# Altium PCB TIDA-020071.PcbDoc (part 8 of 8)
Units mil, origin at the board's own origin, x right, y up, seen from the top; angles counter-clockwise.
Board outline 5750 x 4050 mil, 6 copper layers (Top Layer, GND PLANE-1, SIGNAL LAYER, SIGNAL/POWER LAYER, GND PLANE-2, Bottom Layer), stack 59.616 mil thick; 776 components, 498 nets, 2205 pads, 871 vias.
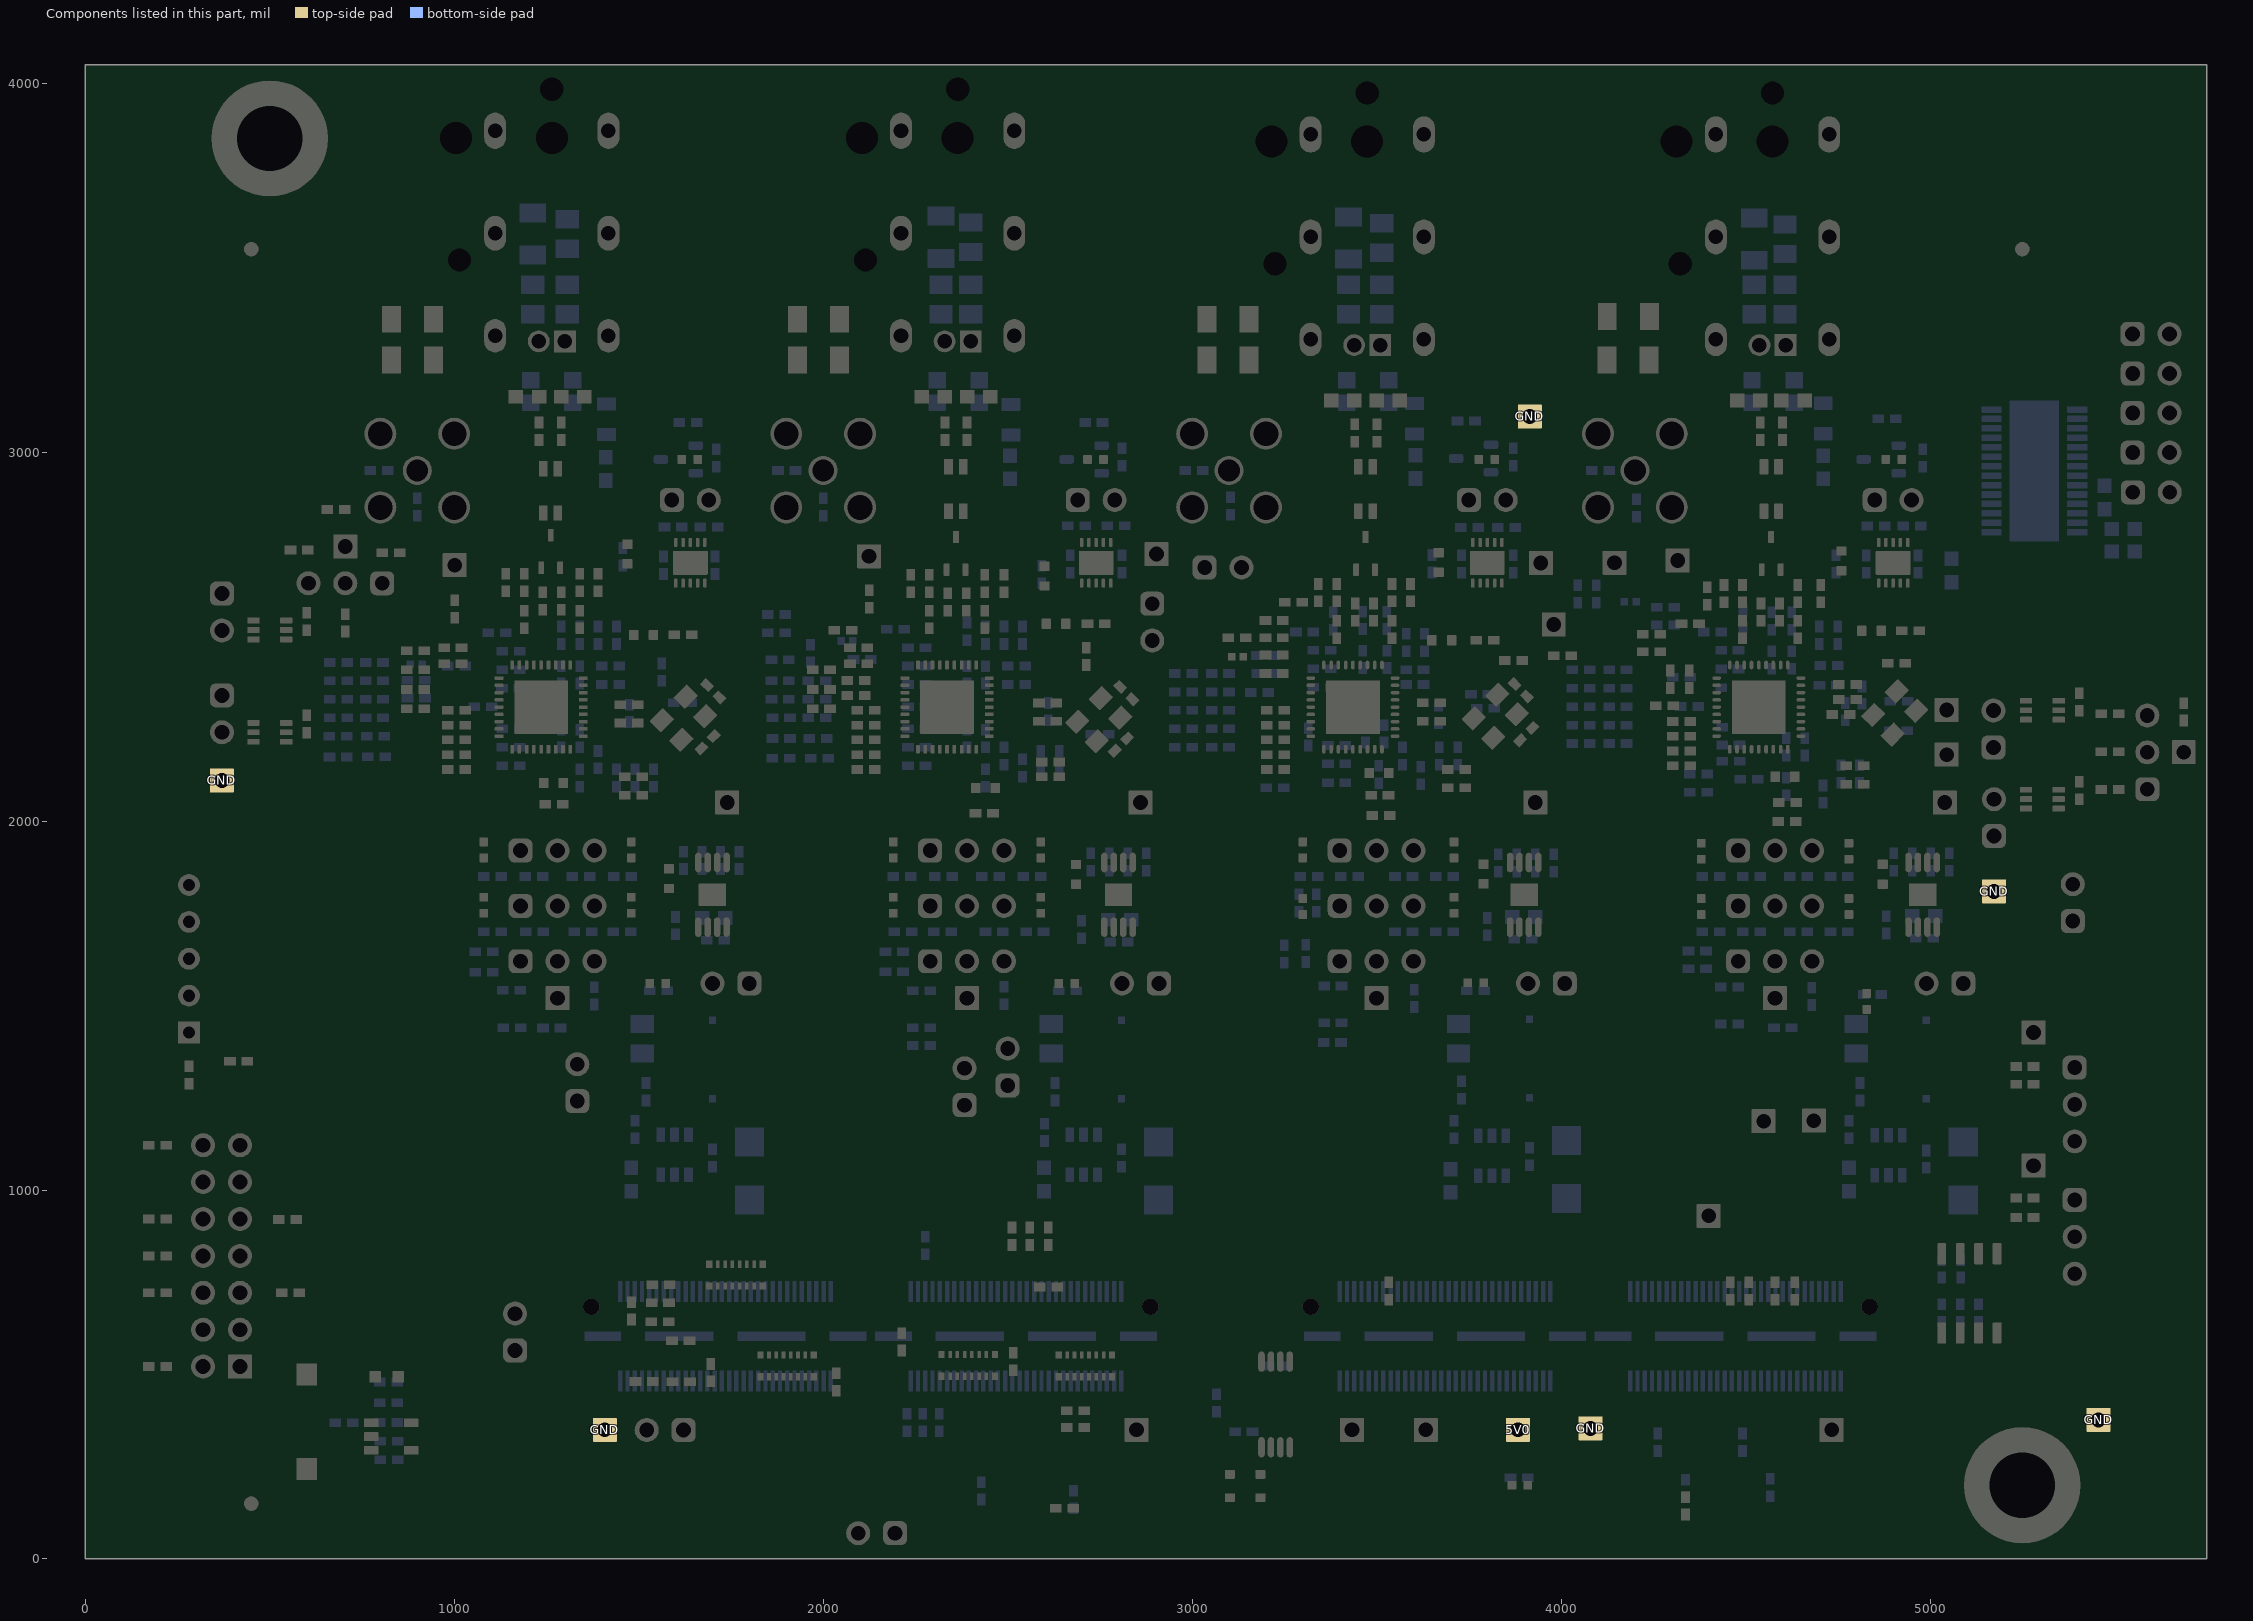
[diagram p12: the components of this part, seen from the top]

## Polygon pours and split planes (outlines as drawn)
GND on Bottom Layer "BOTTOM_LAYER_GND_P145" (solid, remove dead copper, pour order 145): 4467.17,3701.08 4467.44,3700.81 4467.44,3610.7 4491.13,3587.02 4644.4,3587.02 4659.1,3601.72 4659.1,3705.17 4639.77,3724.5 4486.23,3724.5 4484.6,3722.86
NetC154_1 on Bottom Layer "BOTTOM_LAYER_NETC154_1_P148" (solid, remove dead copper, pour order 148): 4533.65,3575.43 4491.63,3575.43 4471.04,3554.84 4471.04,3434.17 4495.8,3409.41 4644.31,3409.41 4664.76,3429.86 4664.76,3543.94 4633.27,3575.43
GND on Bottom Layer "BOTTOM_LAYER_GND_P146" (solid, remove dead copper, pour order 146): 3372.71,3706.71 3372.98,3706.44 3372.98,3616.33 3396.66,3592.65 3549.94,3592.65 3564.64,3607.35 3564.64,3710.8 3545.31,3730.13 3391.76,3730.13 3390.13,3728.49
NetC143_1 on Bottom Layer "BOTTOM_LAYER_NETC143_1_P147" (solid, remove dead copper, pour order 147): 3439.18,3581.06 3397.17,3581.06 3376.58,3560.47 3376.58,3439.8 3401.34,3415.04 3549.85,3415.04 3570.3,3435.49 3570.3,3549.57 3538.81,3581.06
NetC165_1 on Bottom Layer "BOTTOM_LAYER_NETC165_1_P144" (solid, remove dead copper, pour order 144): 2323.83,3582.33 2281.81,3582.33 2261.22,3561.75 2261.22,3441.07 2285.98,3416.32 2434.49,3416.32 2454.94,3436.76 2454.94,3550.84 2423.45,3582.33
GND on Bottom Layer "BOTTOM_LAYER_GND_P149" (solid, remove dead copper, pour order 149): 2257.35,3707.99 2257.62,3707.72 2257.62,3617.6 2281.31,3593.92 2434.58,3593.92 2449.28,3608.62 2449.28,3712.07 2429.95,3731.4 2276.41,3731.4 2274.78,3729.77
GND on Bottom Layer "BOTTOM_LAYER_GND_P150" (solid, remove dead copper, pour order 150): 1163.47,3710.34 1163.74,3710.07 1163.74,3619.95 1187.42,3596.27 1340.7,3596.27 1355.4,3610.97 1355.4,3714.42 1336.07,3733.75 1182.52,3733.75 1180.89,3732.12
NetC173_1 on Bottom Layer "BOTTOM_LAYER_NETC173_1_P151" (solid, remove dead copper, pour order 151): 1229.94,3584.68 1187.92,3584.68 1167.34,3564.1 1167.34,3443.42 1192.1,3418.67 1340.61,3418.67 1361.06,3439.11 1361.06,3553.2 1329.57,3584.68
GND on Bottom Layer "BOTTOM_LAYER_GND_P185" (solid, remove dead copper, pour order 185): 5717.1,3150 26,3150 26,50 5717.1,50
GND720-2 on Bottom Layer "BOTTOM_LAYER_GND720-2_P184" (solid, remove dead copper, pour order 184): 4198.5,3173.44 4198.5,4000 4828.58,4000 4828.43,3173.44
GND720-1 on Bottom Layer "BOTTOM_LAYER_GND720-1_P183" (solid, remove dead copper, pour order 183): 3100,3173.44 3100,4000 3730.08,4000 3729.92,3173.44
GND720-3 on Bottom Layer "BOTTOM_LAYER_GND720-3_P179" (solid, remove dead copper, pour order 179): 1990,3183.44 1990,4010 2620.08,4010 2619.92,3183.44
GND720-4 on Bottom Layer "BOTTOM_LAYER_GND720-4_P182" (solid, remove dead copper, pour order 182): 890.24,3180 890.24,4010 1520.32,4010 1520.16,3180
NetC37_1 on Bottom Layer "BOTTOM_LAYER_NETC37_1_P152" (solid, remove dead copper, pour order 152): 4860.63,1280 4860.63,1209.68 4860.63,1050 5170,1050 5170,1220 5110,1280
NetC3_1 on Bottom Layer "BOTTOM_LAYER_NETC3_1_P154" (solid, remove dead copper, pour order 154): 3780,1280 3780,1209.68 3780,1050 4089.37,1050 4089.37,1220 4029.37,1280
+3V3_REG-4 on Bottom Layer "BOTTOM_LAYER_+3V3_REG-4_P178" (solid, remove dead copper, pour order 178): 1470,1440 1470,1600 1537.01,1665.39 1718.4,1665.39 1824.02,1563.12 1824.02,1440
+3V3_REG-1 on Bottom Layer "BOTTOM_LAYER_+3V3_REG-1_P177" (solid, remove dead copper, pour order 177): 3690,1440 3690,1600 3757.01,1665.39 3938.4,1665.39 4044.02,1563.12 4044.02,1440
+3V3_REG-3 on Bottom Layer "BOTTOM_LAYER_+3V3_REG-3_P172" (solid, remove dead copper, pour order 172): 2580,1440 2580,1600 2647.01,1665.39 2828.4,1665.39 2934.02,1563.12 2934.02,1440
NetC105_1 on Bottom Layer "BOTTOM_LAYER_NETC105_1_P171" (solid, remove dead copper, pour order 171): 1570,1280 1570,1209.68 1570,1050 1879.37,1050 1879.37,1220 1819.37,1280
NetC71_1 on Bottom Layer "BOTTOM_LAYER_NETC71_1_P155" (solid, remove dead copper, pour order 155): 2680,1280 2680,1209.68 2680,1050 2989.37,1050 2989.37,1220 2929.37,1280
+3V3_REG-2 on Bottom Layer "BOTTOM_LAYER_+3V3_REG-2_P153" (solid, remove dead copper, pour order 153): 4760,1440 4760,1600 4827.01,1665.39 5008.4,1665.39 5114.02,1563.12 5114.02,1440
GND on Top Layer "TOP_LAYER_GND_P173" (solid, remove dead copper, pour order 173): 5717.1,3150 26,3150 26,50 5717.1,50
PWM_Main on Top Layer "TOP_LAYER_NONET_P-001" (solid, remove dead copper, pour order 170): 253.05,1317.03 385.09,1317.03 410.13,1342.07 410.13,1444.21 379.38,1474.96 241.65,1474.96 231.23,1464.55 231.23,1338.85
GND720-2 on Top Layer "TOP_LAYER_GND720-2_P169" (solid, remove dead copper, pour order 169): 4198.5,3173.44 4198.5,4000 4828.58,4000 4828.43,3173.44
GND720-1 on Top Layer "TOP_LAYER_GND720-1_P168" (solid, remove dead copper, pour order 168): 3100,3173.44 3100,4000 3730.08,4000 3729.92,3173.44
GND720-3 on Top Layer "TOP_LAYER_GND720-3_P142" (solid, remove dead copper, pour order 142): 1990,3183.44 1990,4010 2620.08,4010 2619.92,3183.44
GND720-4 on Top Layer "TOP_LAYER_GND720-4_P143" (solid, remove dead copper, pour order 143): 890.24,3180 890.24,4010 1520.32,4010 1520.16,3180
GND on GND PLANE-1 "GND_PLANE-1_GND_P174" (solid, remove dead copper, pour order 174): 5717.1,4009.44 26,4009.44 26,50 5717.1,50
GND on GND PLANE-1 "GND_PLANE-1_GND_P159" (solid, remove dead copper, pour order 159): 4500,3520 4643.84,3520 4643.84,2720 4500,2720
GND on GND PLANE-1 "GND_PLANE-1_GND_P156" (solid, remove dead copper, pour order 156): 1180,3350 1350,3350 1350,2727.01 1180,2727.01
GND on GND PLANE-1 "GND_PLANE-1_GND_P158" (solid, remove dead copper, pour order 158): 3410,3520.47 3554.73,3520.47 3554.73,2722.64 3410,2722.64
GND on GND PLANE-1 "GND_PLANE-1_GND_P157" (solid, remove dead copper, pour order 157): 2280,3360 2450,3360 2450,2721.16 2280,2721.16
5V0 on SIGNAL/POWER LAYER "SIGNAL/POWER_LAYER_5V0_P175" (solid, remove dead copper, pour order 175): 5717.1,3150 26,3150 26,50 5717.1,50
Vpu-3 on SIGNAL/POWER LAYER "SIGNAL/POWER_LAYER_VPU-3_P162" (solid, remove dead copper, pour order 162): 1830,2233.82 1830,2276.38 1894.44,2340.82 2094.3,2340.82 2118.3,2316.83 2118.3,2260.52 2145,2233.82 2650,2233.82 2650,2027.51 2370,1747.51 2370,1637.65 2262.35,1530 2221.28,1530 2130,1621.28 2130,1883.82 1830,2183.82
Vpu-4 on SIGNAL/POWER LAYER "SIGNAL/POWER_LAYER_VPU-4_P160" (solid, remove dead copper, pour order 160): 627.67,2189.73 627.67,2207.17 643.3,2222.8 731.42,2222.8 1013.15,1941.07 1131.04,1941.07 1156.39,1915.72 1156.39,1876.25 1424.22,1876.25 1545.72,1997.75 1545.72,2013.58 1535.31,2024 1407.14,2024 1394.55,2011.41 1353.29,2011.41 1286.18,2078.52 1286.18,2141.98 1352.79,2208.59 1540.97,2208.59 1670.6,2078.96 1670.6,1915.65 1279.47,1531.04 1279.35,1520.21 1101.73,1519.96 1000,1621.69 1000,1817.4
Vpu-2 on SIGNAL/POWER LAYER "SIGNAL/POWER_LAYER_VPU-2_P161" (solid, remove dead copper, pour order 161): 4330,2028.52 4423.88,2122.4 4655.46,2122.4 4666.36,2111.5 4815.01,2111.5 4830,2096.51 4830,1829.4 4530.1,1529.5 4396.02,1529.5 4330,1590
Vpu-1 on SIGNAL/POWER LAYER "SIGNAL/POWER_LAYER_VPU-1_P163" (solid, remove dead copper, pour order 163): 2920,2160 2920,2210 3740,2210 3740,2010 3390,1660 3390,1550 3360,1520 3330.46,1520 3240,1610.46 3240,1840
GND on GND PLANE-2 "GND_PLANE-2_GND_P176" (solid, remove dead copper, pour order 176): 5717.1,3150 26,3150 26,50 5717.1,50
GND on GND PLANE-2 "GND_PLANE-2_GND_P164" (solid, remove dead copper, pour order 164): 4500,3520 4643.84,3520 4643.84,2720 4500,2720
GND on GND PLANE-2 "GND_PLANE-2_GND_P165" (solid, remove dead copper, pour order 165): 3410,3520.47 3554.73,3520.47 3554.73,2722.64 3410,2722.64
GND on GND PLANE-2 "GND_PLANE-2_GND_P166" (solid, remove dead copper, pour order 166): 2280,3360 2450,3360 2450,2721.16 2280,2721.16
GND on GND PLANE-2 "GND_PLANE-2_GND_P167" (solid, remove dead copper, pour order 167): 1180,3350 1350,3350 1350,2727.01 1180,2727.01

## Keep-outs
GND PLANE-1:
  circle w10: c450,150 r39.27
GND PLANE-2:
  circle w10: c450,150 r39.27
Keep-Out Layer:
  text ".Layer_Name" at 877,-858.49 h60

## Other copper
Top Layer:
  rectangle net GND: 4450.72,2224.36 4620.01,2393.66
  rectangle net GND: 3350.72,2224.36 3520.01,2393.66
  rectangle net GND: 2250.72,2224.36 2420.01,2393.66
  rectangle net GND: 1150.72,2224.36 1320.01,2393.66
  pour cut-out: 2306.19,3119.3 2413.81,3119.3 2413.81,2987.79 2404.32,2987.79 2404.32,2802.37 2400.9,2802.37 2400.9,2651.33 2313.81,2651.33 2313.81,2697.75 2320.75,2697.75 2320.75,2802.37 2317.33,2802.37 2317.33,2987.79 2306.19,2987.79
  pour cut-out: 4489.7,3340 4660,3340 4660,3150 4490.27,3150
  pour cut-out: 3389.7,3340 3560,3340 3560,3150 3390.27,3150
  pour cut-out: 1206.19,3119.3 1313.81,3119.3 1313.81,2987.79 1304.32,2987.79 1304.32,2802.37 1300.9,2802.37 1300.9,2651.33 1213.81,2651.33 1213.81,2697.75 1220.75,2697.75 1220.75,2802.37 1217.33,2802.37 1217.33,2987.79 1206.19,2987.79
  pour cut-out: 4439,2406 4439,2210.7 4633.7,2210.7 4633.7,2406
  pour cut-out: 3339,2406 3339,2210.7 3533.7,2210.7 3533.7,2406
  pour cut-out: 1139,2406 1139,2210.7 1333.7,2210.7 1333.7,2406
  pour cut-out: 2239,2406 2239,2210.7 2433.7,2210.7 2433.7,2406
  pour cut-out: 1179.42,3350 1349.72,3350 1349.72,3160 1179.99,3160
  pour cut-out: 2279.7,3350 2450,3350 2450,3160 2280.27,3160
  pour cut-out: 4526.82,2927.33 4613.81,2927.33 4613.81,2872.59 4526.82,2872.59
  pour cut-out: 3426.19,2927.33 3513.18,2927.33 3513.18,2872.59 3426.19,2872.59
  pour cut-out: 2316.19,2927.33 2403.18,2927.33 2403.18,2872.59 2316.19,2872.59
  pour cut-out: 1217.33,2922.45 1304.32,2922.45 1304.32,2870 1302.03,2867.71 1217.33,2867.71
  text ".Layer_Name" at 896.98,-852.79 h60
GND PLANE-1:
  text ".Layer_Name" at 905.5,-854.9 h60
SIGNAL LAYER:
  text ".Layer_Name" at 896.98,-852.79 h60
SIGNAL/POWER LAYER:
  text ".Layer_Name" at 888.5,-856.4 h60
GND PLANE-2:
  text ".Layer_Name" at 896.98,-852.79 h60
Bottom Layer:
  text ".Layer_Name" at 896.98,-852.79 h60

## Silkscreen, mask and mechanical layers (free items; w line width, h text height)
Top Overlay:
  drawing of 284 lines, arcs and shapes, not listed
  text "EN PoDL J8" at 5149.22,3309.06 h60
  text "EN PoDL J7" at 5149.22,3200.63 h60
  text "EN PoDL J9" at 5149.22,3089.33 h60
  text "EN PoDL J10" at 5149.22,2981.58 h60
  text "1V0" at 2797.75,2962.25 h60
  text "1V0" at 3861.61,2960.1 h60
  text "1V0" at 4965.16,2957.7 h60
  text "1V0" at 1691.81,2942.6 h60
  text "Diag EN" at 5149.22,2868.9 h60
  text "SoC" at 5542.01,2780.2 h60
  text "MDIO1/2" at 5432.06,2727.24 h60
  text "PHY" at 5535.98,2676.28 h60
  text "PHY" at 203.1,2603.9 h60
  text "SoC" at 5542.68,2581.08 h60
  text "MDIO3/4" at 106.97,2544.06 h60
  text "MDC1/2" at 5452.17,2525.43 h60
  text "SoC" at 206.01,2490.46 h60
  text "PHY" at 5542.68,2472.47 h60
  text "PHY" at 201.65,2331.47 h60
  text "MDC3/4" at 106.13,2273.04 h60
  text "SoC" at 205.52,2215.61 h60
  text "MASTER" at 828.76,1900 h60
  text "MASTER" at 1940.09,1900 h60
  text "MASTER" at 3052.63,1900 h60
  text "MASTER" at 4130,1900 h60
  text "GND" at 344.12,1800.18 h60
  text "MANAGED" at 1865.1,1753.4 h60
  text "MANAGED" at 2993.8,1751.4 h60
  text "MANAGED" at 4081.1,1751.4 h60
  text "MANAGED" at 781.1,1750.4 h60
  text "MC" at 344.12,1704.44 h60
  text "BC" at 344.12,1605.36 h60
  text "WAKE" at 4251.62,1601 h60
  text "WAKE" at 963.92,1600 h60
  text "WAKE" at 2063.93,1599.83 h60
  text "WAKE" at 3176.46,1600 h60
  text "CC" at 344.12,1512.66 h60
  text "3V3" at 1501.18,1498.39 h60
  text "3V3" at 2654.02,1488.37 h60
  text "3V3" at 3737.2,1487.52 h60
  text "3V3" at 4871.64,1466.65 h60
  text "PWN_IN" at 342.38,1407.81 h60
  text "TIDA-020071" at 3150.62,1215.04 h60
  text "GND" at 1013.64,1141.59 h30
  text "IO3_U13" at 682.52,1135.96 h30
  text "TDA4 Quad RGMII daughter card" at 2654.5,1104.2 h60
  text "LED0_U1" at 909.12,1056.33 h30
  text "MC" at 682.52,1052.64 h30
  text "Revision E3" at 3178.56,1002.95 h60
  text "IO4_U13" at 909.85,972.64 h30
  text "IO3_U19" at 681.5,972.06 h30
  text "BC" at 1041.89,895.95 h30
  text "STRP1_U1" at 680.92,895.37 h30
  text "CLKOUT_U13" at 680.92,830.79 h30
  text "IO4_U19" at 908.59,785.67 h30
  text "CC" at 682.52,725.75 h30
  text "CLKOUT_U1" at 849.3,724.11 h30
  text "CLKOUT_U19" at 686.08,657.38 h30
  text "GND" at 1014.79,656.07 h30
  text "RESET" at 758,186.39 h60
  text ".Layer_Name" at 896.98,-852.79 h60
Bottom Overlay:
  lines w6: 843.31,2299.01 843.31,2212.11 871.57,2183.84 871.57,1880.07 860.04,1868.54 609.06,1868.54 586.9,1890.7 586.9,2441.1 635.3,2489.5 820.74,2489.5 844.06,2466.18 844.06,2421.38 844.09,2421.4 ; 956.7,2348.37 958.38,2346.69 958.38,2300.5 ; 1055.69,2466.18 1068.38,2453.49 1078.62,2443.25 1078.62,2381.62 1068.4,2371.4 ; 1126,1887.52 1133.45,1880.07 1136.96,1880.07 1163.76,1880.07 ; 1133.45,1737.52 1140.77,1730.2 1163.76,1730.2 ; 1199.61,2575.62 1199.61,2529.51 1220.5,2508.61 1220.5,2369.38 1212.52,2361.4 ; 1398.65,1880.1 1411.15,1892.6 1430,1892.6 ; 1400.5,1730.2 1407.82,1737.52 1418.11,1737.52 ; 1471.62,2440.5 1522.22,2491.1 1522.22,2513.67 ; 1698.76,2383.81 1711.19,2350.61 ; 1926.38,2472.12 1817.62,2472.12 1813.07,2467.57 1813.07,2063.68 1835.6,2041.15 1848.62,2028.12 1848.62,1901.88 1867.6,1882.9 2100.28,1882.9 2108.6,1891.22 2108.6,2162.7 2045.32,2225.98 2045.32,2406.81 2034.66,2417.47 2000.03,2417.47 ; 2238.62,1928.2 2240.68,1926.14 2240.68,1891.22 2251.03,1880.87 2269.29,1880.87 2273.76,1876.4 ; 2251.03,1741.38 2262.21,1730.2 2273.73,1730.2 ; 2314.7,2196.6 2314.7,2196.65 2322.48,2204.43 2322.48,2583.01 ; 2429.53,2339.93 2364.09,2339.93 2348.62,2355.4 2348.62,2567.55 2364.09,2583.01 2364.09,2805.3 2385.17,2826.38 2448.66,2826.38 2469.5,2805.54 2469.5,2576.55 2460.5,2567.55 2460.5,2563.4 ; 2510.5,1876.4 2532.5,1898.4 2532.5,1919.32 2541.38,1928.2 ; 2516.27,1730.2 2523.59,1737.52 2525.62,1737.52 ; 2802.3,2298.71 2813.59,2265.84 ; 3130,2430.5 2926.76,2430.5 2909.61,2413.35 2909.61,2085.01 2932.51,2062.11 2932.51,1962.45 2943.24,1951.72 3128.64,1951.72 3139.4,1962.48 3139.4,2267.08 3135,2271.48 ; 3139.4,2483.29 3139.37,2483.26 3139.37,2405.52 3145.39,2399.5 ; 3287.42,2339.5 3287.42,2385.55 3291.38,2389.5 ; 3353,1885.65 3362.65,1885.65 3371.9,1876.4 ; 3410,2463.35 3419.21,2472.56 3419.21,2640 ; 3627.9,1876.43 3637.13,1885.65 3647.5,1885.65 ; 3791.18,2265.1 3817.16,2236.32 ; 4358.44,1903.76 4429.41,1903.76 4447.52,1885.65 ; 4358.43,2469.47 4391.28,2469.47 4397.4,2463.35 ; 4435.87,1737.52 4443.74,1729.65 4459.28,1729.65 4461.21,1727.72 ; 4699,1670.76 4710.27,1659.5 4728.62,1659.5 ; 4698.99,1879.02 4707.49,1887.52 4737.85,1887.52 ; 4824.37,2338.02 4901.52,2415.17 ; 4934.04,2504.33 4962.53,2532.83 ; 1522.22,2513.67 1644.71,2513.67 1644.71,2613.65 1522.22,2613.65 1522.22,2513.67 ; 3291.38,2389.5 3291.4,2389.5 ; 3986.61,1983.65 4009.4,1960.87 4183.63,1960.87 4193.4,1970.63 4193.4,1993.67 4193.4,2152.64 4216,2175.24 4216,2446.71 4204.09,2458.62 4031.62,2458.62 4019.71,2446.71 4001.09,2446.71 3986.61,2432.23 3986.61,1983.65 ; 4531.13,2391.38 4531.13,2804.75 4550,2823.62 4639.17,2823.62 4664.99,2797.8 4664.99,2394.44 4640.05,2369.5 4553.01,2369.5 4531.13,2391.38 ; 4903.47,2415.17 5006.45,2415.17 5006.45,2609.99 4903.47,2609.99 4903.47,2415.17
  lines w10: 4901.52,2415.17 4903.47,2415.17
  text ".Layer_Name" at 896.98,-852.79 h60
Top Paste:
  text ".Layer_Name" at 877,-858.49 h60
Bottom Paste:
  text ".Layer_Name" at 877,-858.49 h60
Top Solder:
  text ".Layer_Name" at 877,-858.49 h60
  text ".Layer_Name" at 877,-858.49 h60
Bottom Solder:
  text ".Layer_Name" at 877,-858.49 h60
Drill Guide:
  text ".Layer_Name" at 877,-858.49 h60
M1 Board Outline:
  the board outline again, w10
  text ".Layer_Name" at 842.7,-858.5 h60
M2 Board Dimensions:
  rectangle: 300,-275 425,-150
  rectangle: 425,-400 800,-275
  lines w7: 300,-275 1300,-275 ; 425,-400 425,-150 ; 550,-400 550,-150 ; 800,-400 800,-150 ; 1050,-400 1050,-150 ; 300,-400 1300,-400 1300,-150 300,-150 300,-400
M3 3D STEP Top:
  text ".Layer_Name" at 877,-858.49 h60
M4 3D STEP Bottom:
  text ".Layer_Name" at 877,-858.49 h60
M5 Assembly Top:
  circle w10: c2479.8,2219 r10.81
  circle w10: c1382.52,2213.8 r12.15
  circle w10: c5607.73,2016.49 r8.88
  circle w10: c4408.2,1580 r8.88
  circle w10: c4408.2,1727.72 r8.88
  circle w10: c4408.2,1882.26 r8.88
  circle w10: c3323.59,1569.84 r8.88
  circle w10: c3323.59,1727.72 r8.88
  circle w10: c3322.38,1882.26 r8.88
  circle w10: c2217.14,1571.81 r8.88
  circle w10: c2217.14,1729.78 r8.88
  circle w10: c2215.75,1894.09 r8.88
  circle w10: c1109.1,1659.1 r8.88
  circle w10: c1110.27,1762.6 r8.88
  circle w10: c1110.27,1894.09 r8.88
  circle w10: c888,2671.72 r9.45
  circle w10: c5399.16,1046.61 r9.45
  circle w10: c5415.6,1414.83 r9.45
  circle w10: c2615.16,2868.73 r10.41
  circle w10: c3675.16,2868.73 r10.41
  circle w10: c4775.16,2868.73 r10.41
  circle w10: c1166.26,490.16 r10.41
  circle w10: c1696.66,350.53 r10.41
  circle w10: c2269.84,71.26 r10.41
  circle w10: c2501.26,1208.52 r10.41
  circle w10: c2384.68,1155.16 r10.41
  circle w10: c1515.16,2868.73 r10.41
  circle w10: c369.18,2415.34 r10.41
  circle w10: c369.18,2691.47 r10.41
  circle w10: c1874.84,1561.26 r10.41
  circle w10: c5174.61,1884.47 r10.41
  circle w10: c5171.67,2129.31 r10.41
  circle w10: c5164.84,1561.26 r10.41
  circle w10: c4084.84,1561.26 r10.41
  circle w10: c2984.84,1561.26 r10.41
  lines w6: 320.45,2190.5 320.45,2390.5 420.45,2390.5 420.45,2190.5 320.45,2190.5 ; 320.45,2466.63 320.45,2666.63 420.45,2666.63 420.45,2466.63 320.45,2466.63 ; 1115,515 1215,515 1215,715 1115,715 1115,515 ; 1471.82,299.26 1671.82,299.26 1671.82,399.26 1471.82,399.26 1471.82,299.26 ; 1540,2820 1740,2820 1740,2920 1540,2920 1540,2820 ; 1650,1510 1850,1510 1850,1610 1650,1610 1650,1510 ; 2045,20 2245,20 2245,120 2045,120 2045,20 ; 2333.42,1180 2433.42,1180 2433.42,1380 2333.42,1380 2333.42,1180 ; 2450,1233.36 2550,1233.36 2550,1433.36 2450,1433.36 2450,1233.36 ; 2640,2820 2840,2820 2840,2920 2640,2920 2640,2820 ; 2760,1510 2760,1610 2960,1610 2960,1510 2760,1510 ; 3700,2820 3900,2820 3900,2920 3700,2920 3700,2820 ; 3860,1510 4060,1510 4060,1610 3860,1610 3860,1510 ; 4800,2820 5000,2820 5000,2920 4800,2920 4800,2820 ; 4940,1510 5140,1510 5140,1610 4940,1610 4940,1510 ; 5121.67,2149.31 5221.67,2149.31 5221.67,2349.31 5121.67,2349.31 5121.67,2149.31 ; 5123.35,1909.31 5223.35,1909.31 5223.35,2109.31 5123.35,2109.31 5123.35,1909.31
  lines w10: 8,-930.17 6608,-930.17 ; 8,-726.83 6610,-726.83 ; 8,-523.5 8,-1133.5 4013,-1133.5 6610,-1133.5 6610,-523.5 8.5,-523.5 8.5,-1133.5 1584,-1133.5 ; 2473,-1133.5 2473,-523.5 ; 3740,-726.83 3740,-523.5 ; 4580,-726.83 4580,-523.5 ; 5202,-1140 5202,-937.17
  text "COMPONENTS MARKED 'DNP' SHOULD NOT BE POPULATED." at 1453.5,-318.5 h60
  text "ASSEMBLY VARIANT:" at 1453,-434 h60
  text ".VariantName" at 2489,-434 h60
  text "PCB VIEWED FROM TOP SIDE" at 71.5,-655.67 h60
  text "BOARD #:" at 2548,-655.67 h60
  text ".PRJ_Number" at 3093.5,-655.67 h60
  text "REV:" at 3938,-655.67 h60
  text ".PCB_Rev" at 4229.5,-655.67 h60
  text "SVN REV:" at 4776,-655.67 h60
  text ".VersionControl_RevNumber" at 5282,-655.67 h60
  text "TID #:" at 2548,-859 h60
  text ".TID" at 3093.5,-859 h60
  text ".Layer_Name" at 564.4,-865.3 h60
  text "PLOT NAME =" at 71.5,-1064.34 h60
  text ".plot_File_Name" at 877,-1064.34 h60
  text "GENERATED    :" at 2550,-1064.34 h60
  text ".Print_Date" at 3419.5,-1064.34 h60
  text ".Print_Time" at 4148.5,-1064.34 h60
  text "TEXAS INSTRUMENTS" at 5413,-1064.34 h60
M6 Assembly Bottom:
  lines w10: 7.5,-727.33 6609.5,-727.33 ; 9.5,-930.67 6609.5,-930.67 ; 1415.5,-1140.5 1415.5,-937.67 ; 2037.5,-727.33 2037.5,-524 ; 2877.5,-727.33 2877.5,-524 ; 4144.5,-1134 4144.5,-524 ; 5033.5,-1134 6609,-1134 6609,-524 7.5,-524 7.5,-1134 2604.5,-1134 6609.5,-1134 6609.5,-524
  text "COMPONENTS MARKED 'DNP' SHOULD NOT BE POPULATED." at 6402,-318 h60
  text ".VariantName" at 5358,-434 h60
  text "ASSEMBLY VARIANT:" at 6397,-434 h60
  text ".VersionControl_RevNumber" at 1335.5,-656.17 h60
  text "SVN REV:" at 1841.5,-656.17 h60
  text ".PCB_Rev" at 2388,-656.17 h60
  text "REV:" at 2679.5,-656.17 h60
  text ".PRJ_Number" at 3524,-656.17 h60
  text "BOARD #:" at 4069.5,-656.17 h60
  text "PCB VIEWED FROM BOTTOM SIDE" at 6546,-656.17 h60
  text ".Layer_Name" at 5895.7,-847.6 h60
  text ".TID" at 3524,-859.5 h60
  text "TID #:" at 4069.5,-859.5 h60
  text "TEXAS INSTRUMENTS" at 1204.5,-1064.84 h60
  text ".Print_Time" at 2469,-1064.84 h60
  text ".Print_Date" at 3198,-1064.84 h60
  text "GENERATED    :" at 4067.5,-1064.84 h60
  text ".plot_File_Name" at 5740.5,-1064.84 h60
  text "PLOT NAME =" at 6546,-1064.84 h60
M9 Title Sheet:
  drawing of 57 lines, arcs and shapes, not listed
  text "1" at 1039.84,8036.5 h70
  text "2" at 3535.5,8036.5 h70
  text "3" at 6024.84,8036.5 h70
  text "4" at 8531.51,8036.5 h70
  text "5" at 11030.5,8036.5 h70
  text "6" at 13535.5,8036.5 h70
  text "A" at -116.5,6893.5 h70
  text "A" at 14683.5,6893.5 h70
  text "B" at -116.5,4513.5 h70
  text "B" at 14683.5,4513.5 h70
  text "C" at -116.5,2138.5 h70
  text "C" at 14683.5,2138.5 h70
  text "PROJECT TITLE:" at 11643.5,277.5 h45
  text ".PRJ_Title" at 11693.5,144.17 h70
  text "DESIGNED FOR:" at 11643.5,-23.5 h45
  text ".PRJ_Customer" at 11693.5,-163.5 h70
  text "D" at -116.5,-231.5 h70
  text "D" at 14683.5,-231.5 h70
  text "FILE NAME:" at 11643.5,-323.5 h45
  text ".PCB_File_Name_No_Path" at 11693.5,-443.5 h70
  text "Texas Instruments (TI) and/or its licensors do not warrant the accuracy or completeness of this specification" at 6674,-605.34 h45
  text "ENGINEER:" at 11643.5,-613.5 h45
  text "LAYOUT BY:" at 13148.5,-613.5 h45
  text "or any information contained therein. TI and/or its licensors do not warrant that this design will meet" at 6629.01,-718 h45
  text ".PRJ_Engineer" at 11693.5,-768.49 h70
  text ".PCB_Layout" at 13199,-768.49 h70
  text "the specifications, will be suitable for your application or fit for any particular purpose, or will operate in" at 6629.01,-830.67 h45
  text "ALTIUM DESIGNER VERSION:" at 13148.5,-923.5 h45
  text "an implementation. TI and/or its licensors do not warrant that the design is production worthy. You should" at 6629.01,-943.34 h45
  text "completely validate and test your design implementation to confirm the system functionality for your application." at 6674,-1056 h45
  text ".print_Scale" at 11693.5,-1056.83 h70
  text ".Application_BuildNumber" at 13199,-1056.83 h70
  text "1" at 1039.84,-1263.5 h70
  text "2" at 3535.5,-1263.5 h70
  text "3" at 6024.84,-1263.5 h70
  text "4" at 8531.51,-1263.5 h70
  text "5" at 11030.5,-1263.5 h70
  text "6" at 13535.5,-1263.5 h70
M10 Fab Notes:
  drawing of 189 lines, arcs and shapes, not listed
  text "DESIGN INFORMATION" at 12682.02,6356.17 h60
  text "MIN. TRACK WIDTH:" at 12037.46,6224.05 h60
  text "4" at 13133.7,6224.05 h60
  text "MIL" at 13288.46,6224.05 h60
  text "MIN. CLEARANCE:" at 12037.46,6099.92 h60
  text "MIL" at 13288.46,6099.92 h60
  text "7" at 13152.2,6098.9 h60
  text "19.685" at 12926.2,5976.8 h60
  text "MIN. VIA PAD SIZE:" at 12037.46,5975.8 h60
  text "MIL" at 13288.46,5975.8 h60
  text "0.05mm (2MIL)" at 12732.46,5845.9 h60
  text "MINIMUM ANNULAR RING" at 11708.23,5837.67 h60
  text "EXTERNAL" at 13440.46,5837.67 h60
  text "PER" at 11908.23,5727.55 h60
  text "IPC-D-275 CLASS 2 LEVEL C" at 12128.23,5727.54 h60
  text "MIL, HOLES" at 13616.46,5627.07 h60
  text "+/-" at 13224,5618.48 h60
  text "+/-" at 14078,5618.48 h60
  text "REGISTRATION TOLERANCES:" at 11708.23,5617.42 h60
  text "METAL" at 12908,5617.42 h60
  text "5" at 13484.2,5617.42 h60
  text "3" at 14317.2,5617.42 h60
  text "MIL" at 14433.46,5617.42 h60
  text "HOLE SIZE TOLERANCE (UNLESS OTHERWISE SPECIFIED):" at 11708.23,5519.1 h60
  text "+/-" at 14078,5516.23 h60
  text "3" at 14317.2,5515.17 h60
  text "MIL" at 14433.46,5515.17 h60
  text "MATERIAL:" at 11633.46,5377.52 h60
  text "FR-4 High Tg" at 12619.9,5248.99 h60
  text "IT180A" at 13941.96,5241.01 h60
  text "X" at 13362.96,5237.81 h60
  text "FR-408" at 12054.46,5236.49 h60
  text "OTHER" at 13542.46,5236.49 h60
  text "62 MIL (1.6mm) +/-10%" at 12374.56,5093.46 h60
  text "X" at 12254.46,5091.01 h60
  text "THICKNESS:" at 11708.23,5085.24 h60
  text "OTHER" at 13659.46,5085.24 h60
  text "TOLERANCE:" at 11708.23,4946.92 h60
  text "X" at 12556.46,4946.92 h60
  text "ANSI IPC-6012 TYPE 3 CLASS 2" at 12734.48,4946.92 h60
  text "OTHER +/-" at 12734.46,4802.73 h60
  text "BOW & TWIST:" at 11708.23,4657.54 h60
  text "X" at 12556.46,4657.54 h60
  text "ANSI IPC-6012 TYPE 3 CLASS 2" at 12734.48,4657.54 h60
  text "OTHER +/-" at 12734.46,4510.85 h60
  text "DRILLING:" at 11633.46,4380.23 h60
  text "NC_DRILL FILES" at 13394.46,4275.04 h60
  text "REFERENCE:" at 11708.23,4271.1 h60
  text "X" at 12365.46,4271.01 h60
  text "AS SHOWN" at 12543.46,4271.1 h60
  text "X" at 13266.46,4271.1 h60
  text "OTHER" at 13692.46,4128.85 h60
  text "PTH COPPER THICKNESS:" at 11707.91,4125.32 h60
  text "X" at 12847.14,4125.32 h60
  text "20-30 um" at 12975.14,4125.32 h60
  text "BOARD FINISH:" at 11633.46,3977.72 h60
  text "SILKSCREEN:" at 11788.68,3867.6 h60
  text "X" at 12746.46,3867.6 h60
  text "TOP" at 12863.46,3867.6 h60
  text "X" at 13256.46,3867.6 h60
  text "BOTTOM" at 13374.46,3867.6 h60
  text "SILKSCREEN COLOR:" at 11788.68,3712.41 h60
  text "X" at 12745.46,3712.41 h60
  text "WHITE" at 12863.46,3712.41 h60
  text "OTHER" at 13374.46,3712.41 h60
  text "X" at 12876.46,3568.96 h60
  text "GREEN" at 12994.46,3568.96 h60
  text "OTHER" at 13612.46,3568.96 h60
  text "SOLDER RESIST COLOR:" at 11788.68,3562.09 h60
  text "X" at 12876.46,3414.71 h60
  text "MATTE" at 12994.46,3414.71 h60
  text "SEMI-GLOSS" at 13612,3414.07 h60
  text "IMMERSION GOLD (ENIG)" at 12694.46,3241.94 h60
  text "ENEPIG" at 14032,3234.72 h60
  text "SURFACE FINISH:" at 11633.46,3233.72 h60
  text "X" at 12516.46,3233.72 h60
  text "IMM. TIN/SILVER OR EQUIV" at 11963,3096.4 h60
  text "OTHER" at 13394.46,3092.46 h60
  text "ARRAY/PANEL:" at 11633.46,2937.09 h60
  text "CUT AND TRIM PER M1 BOARD OUTLINE" at 12694.46,2928.87 h60
  text "N.C. ROUTE" at 12694.46,2792.9 h60
  text "X" at 13382.46,2792.9 h60
  text "V. SCORE" at 13560.46,2792.9 h60
  text "CERTIFICATION:" at 11633.46,2663.77 h60
  text "MATERIALS AND WORKMANSHIP FOR ALL PCBS" at 12358.46,2663.77 h60
  text "TO MEET OR EXCEED THE REQUIREMENTS OF:" at 12358.46,2569.71 h60
  text "X" at 11995.97,2441.08 h60
  text "ANSI IPC-A-600F CLASS ->" at 12123.96,2441.08 h60
  text "X" at 13771.97,2441.08 h60
  text "2" at 13881.96,2441.08 h60
  text "1" at 13566.96,2439.58 h60
  text "3" at 14235.96,2439.58 h60
  text "X" at 12807.97,2293.39 h60
  text "RoHS" at 12935.96,2293.39 h60
  text "OTHER" at 13580.36,2293.39 h60
  text "PER ORDER" at 13977.42,2293.39 h60
  text "ALL BOARDS MUST MEET OR EXCEED UL94-V0 REQUIREMENTS." at 11661,2139.57 h60
  text "PCB MUST BEAR THE UL94V-0 UL REGISTERED MATERIAL ID NUMBER" at 11661,2023.5 h60
  text "ADDITIONAL REQUIREMENTS:" at 11633.46,1854.08 h60
  text "MICROSECTION:" at 11708.23,1746.95 h60
  text "YES" at 12613.96,1746.95 h60
  text "REQUIRED" at 13475.46,1602.62 h60
  text "BARE BOARD ELEC. TEST:" at 11708.23,1599.76 h60
  text "NONE" at 13013.96,1599.76 h60
  text "X" at 13357.46,1599.76 h60
  text "PER ORDER" at 14067.46,1599.76 h60
  text "XX MIL VIAS REQUIRE NON-CONDUCTIVE FILL AND PLANARIZE" at 11876.38,1394.82 h59
  text "XX MIL VIAS REQUIRE CONDUCTIVE FILL AND PLANARIZE" at 11884.38,1290.84 h60
  text "OUTER XX MIL TRACES REQUIRE 50 OHM SINGLE-ENDED IMPEDANCE" at 11883.39,1127.46 h58
  text "LAYER 2 & 3 (INNER LAYERS) XX MIL WIDE, XX MIL SPACE / TRACES REQUIRE 100 OHM DIFFERENTIAL IMPEDANCE" at 11875.39,891.74 h60
  text "Note:" at 5964.06,621.45 h40
  text "1.All vias are tented unless otherwise mask is opened in gerbers" at 5970.06,509.45 h40
  text "2.Vendor may adjust soldermask wherever the soldermask pads are same size(1:1)" at 5972.06,390.45 h40
  text "As per the manufacturing capabilities and all other soldermask pads  / shall not be modified," at 6033.76,220.77 h40
  text "Provided no adjacent copper is exposed and  no conflict is  produced  / with any stated\"Via tenting/covering requirements\"" at 6045.25,64.88 h40
  text "3.All vias on pad should be filled with non conductive epoxy ." at 5958.06,2.15 h40
M11 Gerber Information:
  lines w10: 8,-930.17 6608,-930.17 ; 8,-726.83 6610,-726.83 ; 8,-523.5 8,-1133.5 4013,-1133.5 6610,-1133.5 6610,-523.5 8.5,-523.5 8.5,-1133.5 1584,-1133.5 ; 2473,-1133.5 2473,-523.5 ; 3740,-726.83 3740,-523.5 ; 4580,-726.83 4580,-523.5 ; 5202,-1140 5202,-937.17
  text "ALL ARTWORK VIEWED FROM TOP SIDE" at 71.5,-655.67 h60
  text "BOARD #:" at 2548,-655.67 h60
  text ".PRJ_Number" at 3093.5,-655.67 h60
  text "REV:" at 3938,-655.67 h60
  text ".PCB_Rev" at 4229.5,-655.67 h60
  text "SVN REV:" at 4776,-655.67 h60
  text ".VersionControl_RevNumber" at 5282,-655.67 h60
  text "LAYER NAME =" at 71.5,-858.49 h60
  text "TID #:" at 2548,-859 h60
  text ".TID" at 3093.5,-859 h60
  text "PLOT NAME =" at 71.5,-1064.34 h60
  text ".plot_File_Name" at 877,-1064.34 h60
  text "GENERATED    :" at 2550,-1064.34 h60
  text ".Print_Date" at 3419.5,-1064.34 h60
  text ".Print_Time" at 4148.5,-1064.34 h60
  text "TEXAS INSTRUMENTS" at 5413,-1064.34 h60
M12 Stackup:
  drawing of 427 lines, arcs and shapes, not listed
  text "IMPEDANCE INFORMATION:" at 7708.3,6700 h60
  text "50 OHM+/-10%" at 8548.1,6569.1 h30
  text "100 OHM+/- 10%" at 9059.9,6568.1 h30
  text "REFERENCE" at 9614.2,6565.3 h40
  text "LAYERS" at 7757.1,6520.2 h45
  text "WIDTH" at 8993.3,6495.2 h40
  text "WIDTH" at 8637.8,6492.7 h40
  text "SPACE" at 9261.2,6492.7 h40
  text "LAYERS" at 9667.2,6486.3 h40
  text "L1 TOP LAYER" at 7642,6379.3 h40
  text "L2 GND PLANE-1" at 9571.9,6379.3 h40
  text "6 MILS" at 8637.8,6375.7 h40
  text "4 MILS" at 8960.2,6374.1 h40
  text "8 MILS" at 9252.8,6374.1 h40
  text "L3 SIGNAL LAYER" at 7642,6140.9 h40
  text "L2 GND PLANE-1" at 9571.9,6140.9 h40
  text "7 MILS" at 8645.1,6137.3 h40
  text "-" at 8967.5,6135 h40
  text "-" at 9024.3,6135 h40
  text "-" at 9078.3,6135 h40
  text "-" at 9260.1,6135 h40
  text "-" at 9305.8,6135 h40
  text "-" at 9362.6,6135 h40
  text "L5 GND PLANE-2" at 9571.9,5832 h40
  text "7 MILS" at 8640.5,5828.4 h40
  text "-" at 8962.9,5826.1 h40
  text "-" at 9019.7,5826.1 h40
  text "-" at 9073.7,5826.1 h40
  text "-" at 9255.5,5826.1 h40
  text "-" at 9301.2,5826.1 h40
  text "-" at 9358,5826.1 h40
  text "L4 SIGNAL/POWER LAYER" at 7642,5821 h40
  text "L6 BOTTOM LAYER" at 7642,5534.7 h40
  text "L5 GND PLANE-2" at 9571.9,5534.7 h40
  text "6 MILS" at 8627.7,5531.1 h40
  text "4 MILS" at 8950.1,5529.5 h40
  text "8 MILS" at 9242.7,5529.5 h40
  text "Layer" at 6465.36,5231.6 h60
  text "Name" at 6875.27,5231.6 h60
  text "Material" at 8064.93,5231.6 h60
  text "Thickness" at 8924.7,5231.6 h60
  text "Constant" at 9574.54,5231.6 h60
  text "Board Layer Stack" at 10144.4,5231.6 h60
  text "Top Overlay" at 6875.27,5111.6 h60
  text "Top Solder" at 6875.27,4991.6 h60
  text "Solder Resist" at 8064.93,4991.6 h60
  text "0.40mil" at 8924.7,4991.6 h60
  text "3.5" at 9574.54,4991.6 h60
  text "1" at 6465.36,4871.6 h60
  text "Top Layer" at 6875.27,4871.6 h60
  text "1.40mil" at 8924.7,4871.6 h60
  text "Dielectric 1" at 6875.27,4751.6 h60
  text "IT180A" at 8064.93,4751.6 h60
  text "3.94mil" at 8924.7,4751.6 h60
  text "4.1" at 9574.54,4751.6 h60
  text "2" at 6465.36,4631.6 h60
  text "GND PLANE-1" at 6875.27,4631.6 h60
  text "1.40mil" at 8924.7,4631.6 h60
  text "Dielectric 2" at 6875.27,4511.6 h60
  text "IT180A" at 8064.93,4511.6 h60
  text "5.91mil" at 8924.7,4511.6 h60
  text "4.1" at 9574.54,4511.6 h60
  text "3" at 6465.36,4391.6 h60
  text "SIGNAL LAYER" at 6875.27,4391.6 h60
  text "1.40mil" at 8924.7,4391.6 h60
  text "Dielectric 3" at 6875.27,4271.6 h60
  text "IT180A" at 8064.93,4271.6 h60
  text "31.50mil" at 8924.7,4271.6 h60
  text "4.1" at 9574.54,4271.6 h60
  text "4" at 6465.36,4151.6 h60
  text "SIGNAL/POWER LAYER" at 6875.27,4151.6 h60
  text "1.42mil" at 8924.7,4151.6 h60
  text "Dielectric 5" at 6875.27,4031.6 h60
  text "IT180A" at 8064.93,4031.6 h60
  text "5.91mil" at 8924.7,4031.6 h60
  text "4.1" at 9574.54,4031.6 h60
  text "5" at 6465.36,3911.6 h60
  text "GND PLANE-2" at 6875.27,3911.6 h60
  text "1.42mil" at 8924.7,3911.6 h60
  text "Dielectric 4" at 6875.27,3791.6 h60
  text "IT180A" at 8064.93,3791.6 h60
  text "3.94mil" at 8924.7,3791.6 h60
  text "4.1" at 9574.54,3791.6 h60
  text "6" at 6465.36,3671.6 h60
  text "Bottom Layer" at 6875.27,3671.6 h60
  text "1.40mil" at 8924.7,3671.6 h60
  text "Bottom Solder" at 6875.27,3551.6 h60
  text "Solder Resist" at 8064.93,3551.6 h60
  text "0.40mil" at 8924.7,3551.6 h60
  text "3.5" at 9574.54,3551.6 h60
  text "Bottom Overlay" at 6875.27,3431.6 h60
M13 Component Bodies Top:
  text ".Layer_Name" at 877,-858.49 h60
M14 Component Bodies Bottom:
  text ".Layer_Name" at 877,-858.49 h60
M15 Courtyards Top:
  text ".Layer_Name" at 877,-858.49 h60
M16 Courtyards Bottom:
  text ".Layer_Name" at 877,-858.49 h60
Drill Drawing:
  drawing of 180 lines, arcs and shapes, not listed
  text "Symbol" at 6660.29,3152.41 h72
  text "Quantity" at 6960.62,3152.41 h72
  text "Finished Hole Size" at 7292.49,3152.41 h72
  text "Plated" at 7928.52,3152.41 h72
  text "Hole Type" at 8187.5,3152.41 h72
  text "Drill Layer Pair" at 8562.42,3152.41 h72
  text "Routed Path Length" at 9286.75,3152.41 h72
  text "Hole Length" at 9963.81,3152.41 h72
  text "105" at 6960.62,3028.09 h60
  text "7.87mil (0.200mm)" at 7292.49,3028.09 h60
  text "PTH" at 7928.52,3028.09 h60
  text "Round" at 8187.5,3028.09 h60
  text "Top Layer - Bottom Layer" at 8562.42,3028.09 h60
  text "-" at 9286.75,3028.09 h60
  text "-" at 9963.81,3028.09 h60
  text "661" at 6960.62,2903.77 h60
  text "8.00mil (0.203mm)" at 7292.49,2903.77 h60
  text "PTH" at 7928.52,2903.77 h60
  text "Round" at 8187.5,2903.77 h60
  text "Top Layer - Bottom Layer" at 8562.42,2903.77 h60
  text "-" at 9286.75,2903.77 h60
  text "-" at 9963.81,2903.77 h60
  text "105" at 6960.62,2779.45 h60
  text "12.00mil (0.305mm)" at 7292.49,2779.45 h60
  text "PTH" at 7928.52,2779.45 h60
  text "Round" at 8187.5,2779.45 h60
  text "Top Layer - Bottom Layer" at 8562.42,2779.45 h60
  text "-" at 9286.75,2779.45 h60
  text "-" at 9963.81,2779.45 h60
  text "A" at 6635.01,2769.46 h55.25
  text "5" at 6960.62,2655.13 h60
  text "33.47mil (0.850mm)" at 7292.49,2655.13 h60
  text "PTH" at 7928.52,2655.13 h60
  text "Round" at 8187.5,2655.13 h60
  text "Top Layer - Bottom Layer" at 8562.42,2655.13 h60
  text "-" at 9286.75,2655.13 h60
  text "-" at 9963.81,2655.13 h60
  text "B" at 6635.01,2645.14 h55.25
  text "8" at 6960.62,2530.81 h60
  text "39.37mil (1.000mm)" at 7292.49,2530.81 h60
  text "PTH" at 7928.52,2530.81 h60
  text "Round" at 8187.5,2530.81 h60
  text "Top Layer - Bottom Layer" at 8562.42,2530.81 h60
  text "-" at 9286.75,2530.81 h60
  text "-" at 9963.81,2530.81 h60
  text "8" at 6960.62,2406.49 h60
  text "39.37mil (1.000mm)" at 7292.49,2406.49 h60
  text "PTH" at 7928.52,2406.49 h60
  text "Slot" at 8187.5,2406.49 h60
  text "Top Layer - Bottom Layer" at 8562.42,2406.49 h60
  text "30.51mil (0.775mm)" at 9286.75,2406.49 h60
  text "69.88mil (1.775mm)" at 9963.81,2406.49 h60
  text "8" at 6960.62,2282.17 h60
  text "39.37mil (1.000mm)" at 7292.49,2282.17 h60
  text "PTH" at 7928.52,2282.17 h60
  text "Slot" at 8187.5,2282.17 h60
  text "Top Layer - Bottom Layer" at 8562.42,2282.17 h60
  text "35.04mil (0.890mm)" at 9286.75,2282.17 h60
  text "74.41mil (1.890mm)" at 9963.81,2282.17 h60
  text "8" at 6960.62,2157.85 h60
  text "39.37mil (1.000mm)" at 7292.49,2157.85 h60
  text "PTH" at 7928.52,2157.85 h60
  text "Slot" at 8187.5,2157.85 h60
  text "Top Layer - Bottom Layer" at 8562.42,2157.85 h60
  text "39.37mil (1.000mm)" at 9286.75,2157.85 h60
  text "78.74mil (2.000mm)" at 9963.81,2157.85 h60
  text "149" at 6960.62,2033.53 h60
  text "40.00mil (1.016mm)" at 7292.49,2033.53 h60
  text "PTH" at 7928.52,2033.53 h60
  text "Round" at 8187.5,2033.53 h60
  text "Top Layer - Bottom Layer" at 8562.42,2033.53 h60
  text "-" at 9286.75,2033.53 h60
  text "-" at 9963.81,2033.53 h60
  text "4" at 6960.62,1909.21 h60
  text "45.28mil (1.150mm)" at 7292.49,1909.21 h60
  text "NPTH" at 7928.52,1909.21 h60
  text "Round" at 8187.5,1909.21 h60
  text "Top Layer - Bottom Layer" at 8562.42,1909.21 h60
  text "-" at 9286.75,1909.21 h60
  text "-" at 9963.81,1909.21 h60
  text "4" at 6960.62,1784.89 h60
  text "59.06mil (1.500mm)" at 7292.49,1784.89 h60
  text "PTH" at 7928.52,1784.89 h60
  text "Round" at 8187.5,1784.89 h60
  text "Top Layer - Bottom Layer" at 8562.42,1784.89 h60
  text "-" at 9286.75,1784.89 h60
  text "-" at 9963.81,1784.89 h60
  text "8" at 6960.62,1660.57 h60
  text "62.99mil (1.600mm)" at 7292.49,1660.57 h60
  text "NPTH" at 7928.52,1660.57 h60
  text "Round" at 8187.5,1660.57 h60
  text "Top Layer - Bottom Layer" at 8562.42,1660.57 h60
  text "-" at 9286.75,1660.57 h60
  text "-" at 9963.81,1660.57 h60
  text "16" at 6960.62,1536.25 h60
  text "66.93mil (1.700mm)" at 7292.49,1536.25 h60
  text "PTH" at 7928.52,1536.25 h60
  text "Round" at 8187.5,1536.25 h60
  text "Top Layer - Bottom Layer" at 8562.42,1536.25 h60
  text "-" at 9286.75,1536.25 h60
  text "-" at 9963.81,1536.25 h60
  text "8" at 6960.62,1411.93 h60
  text "86.61mil (2.200mm)" at 7292.49,1411.93 h60
  text "NPTH" at 7928.52,1411.93 h60
  text "Round" at 8187.5,1411.93 h60
  text "Top Layer - Bottom Layer" at 8562.42,1411.93 h60
  text "-" at 9286.75,1411.93 h60
  text "-" at 9963.81,1411.93 h60
  text "2" at 6960.62,1287.61 h60
  text "177.17mil (4.500mm)" at 7292.49,1287.61 h60
  text "PTH" at 7928.52,1287.61 h60
  text "Round" at 8187.5,1287.61 h60
  text "Top Layer - Bottom Layer" at 8562.42,1287.61 h60
  text "-" at 9286.75,1287.61 h60
  text "-" at 9963.81,1287.61 h60
  text "1099 Total" at 6960.62,1163.29 h60
  text "Slot definitions :" at 6660.29,1076.27 h60
  text "Routed Path Length" at 7111.01,1076.27 h60
  text "= Calculated from tool start centre position to tool end centre position." at 7650.74,1076.27 h60
  text "Hole Length" at 7111.01,1026.54 h60
  text "= Routed Path Length + Tool Size = Slot length as defined in the PCB layout" at 7450.94,1026.54 h60
  text "TOLERANCE :-" at 9584.24,853 h50
  text "FOR 7.874  MIL DRILL  +0/-7.874 MIL" at 9639.2,693.16 h50
  text "FOR 8  MIL DRILL  +0/-8 MIL" at 9641.8,605.24 h50
  text "FOR 12  MIL DRILL  +0/-12 MIL" at 9637,511.5 h50
  text "FOR PTH +/- 3MIL" at 9632.2,434.62 h50
  text "FOR NPTH +/- 2MIL" at 9632.2,357.77 h50
  text ".Layer_Name" at 877,-858.49 h60
Mechanical 17:
  text ".Layer_Name" at 877,-858.49 h60
Mechanical 18:
  text ".Layer_Name" at 877,-858.49 h60
Mechanical 19:
  text ".Layer_Name" at 877,-858.49 h60

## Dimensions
5750,0 to 5750,4050 on M2 Board Dimensions
0,0 to 5750,0 on M2 Board Dimensions
300,-400 to 1300,-400 on M2 Board Dimensions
